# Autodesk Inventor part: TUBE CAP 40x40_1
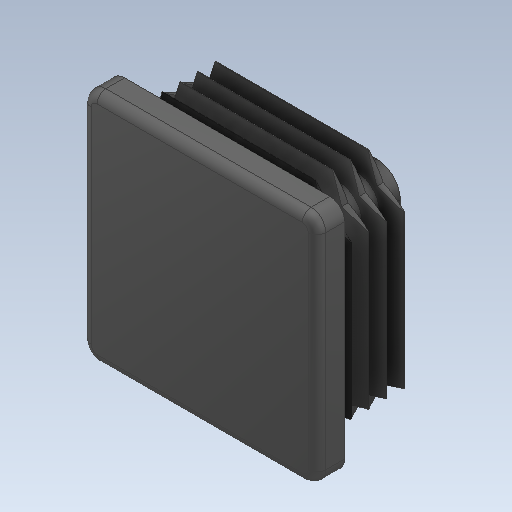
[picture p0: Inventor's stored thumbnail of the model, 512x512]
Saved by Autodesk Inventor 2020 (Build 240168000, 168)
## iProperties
Created: 1900-01
Part Number: TUBE CAP 40x40_1
Material: Générique
Document SubType Name: Modeling
Designer: bruno
Density: 1 g/cm^3
Appearance: Par défaut
Author: bruno
Revision Number: ANYUNSPECIFIED
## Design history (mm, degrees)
feature "Base1"
node "Solide1"
